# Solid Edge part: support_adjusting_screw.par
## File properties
Title: Support adjusting screw
Author: Robert a Rhodes jr
Template: Normal.par
Last saved by: TIET
Revision: 16
Application: Solid Edge
Accuracy: 0.99
Material: aluminum
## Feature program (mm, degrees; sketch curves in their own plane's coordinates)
sketch for "unnamed Protrusion 1" plane through (0, 0, 0) normal (0, -1, 0) x-axis (1, 0, 0)
  circle centre (0, 0) radius 38.1
extrude "unnamed Protrusion 1" add finite 584.2 along +normal
sketch for "ExtrudedCutout_1" plane through (0, -520.7, 0) normal (0, -1, 0) x-axis (1, 0, 0)
extrude "ExtrudedCutout_1" cut finite 76.2 along +normal  Plane_Distance = 63.5 mm
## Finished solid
Body 1: solid body, 5 faces, 4 edges, 0 vertices.
  Faces by surface: plane 3, cylinder 2
  Edges by curve: circle 4
Bounding box of the edges (mm): 76.200 x 584.200 x 76.200, from (-38.1, -584.2, -38.1) to (38.1, 0, 38.1).
Cylindrical faces by radius (mm): R25.4 x1, R38.1 x1
Planar faces by outward normal: +y 1, -y 2
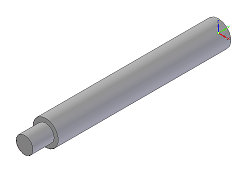
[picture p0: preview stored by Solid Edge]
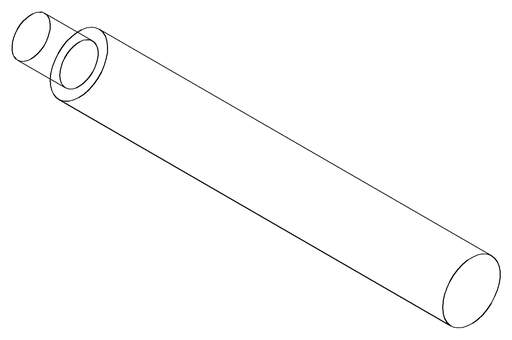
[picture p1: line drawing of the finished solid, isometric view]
